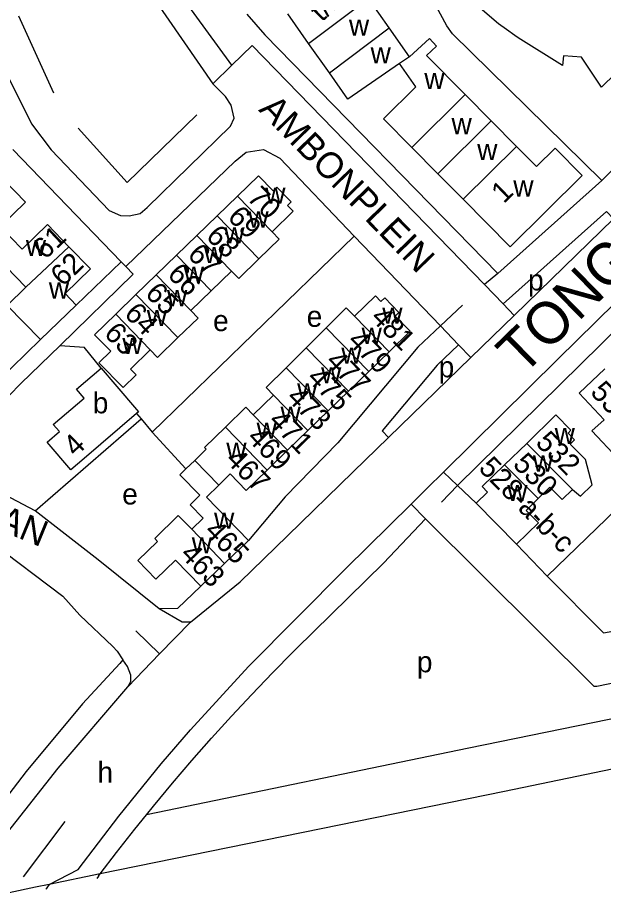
# Model space of a CAD drawing. Extents: x 162883 to 165538, y 383986 to 385172.
# Drawn here: x 163883.1 to 163994.9, y 384146.8 to 384315.2 of the extents above; entities that cross this region are included whole.
import ezdxf

# ---------------------------------------------------------------- set-up
doc = ezdxf.new("R2010")
doc.units = 0
for name, color, linetype in [('BLT_Basislijn', 7, 'Continuous'), ('BLT_Bebouwing', 7, 'Continuous'), ('BLT_Centroide', 7, 'Continuous'), ('BLT_Huisnummer', 7, 'Continuous'), ('BLT_Huisnummer_ tussenligend', 7, 'Continuous'), ('BLT_Huisnummer_reeks', 7, 'Continuous'), ('BLT_Onderverdeling_panden', 7, 'Continuous'), ('BLT_Spoorlijn', 7, 'Continuous'), ('BLT_Straatnaam', 7, 'Continuous'), ('BLT_Straatnaam_hoofdweg', 7, 'Continuous'), ('BLT_Vlakafsluiter', 7, 'Continuous')]:
    doc.layers.add(name, color=color, linetype=linetype)

msp = doc.modelspace()

# ---------------------------------------------------------------- linework, layer by layer
at = {"layer": 'BLT_Basislijn'}
for p, q in [((163924.02, 384306.15), (163911.31, 384323.59)), ((163907.2, 384321.69), (163920.41, 384302.58)), ((163883.27, 384315.54), (163889.98, 384300.83)), ((164013.39, 384302.89), (163994.61, 384284.11)), ((163904.06, 384283.71), (163917.36, 384296.67)), ((163894.71, 384294.1), (163904.06, 384283.71)), ((163994.61, 384284.11), (163974.78, 384266.34)), ((163908.8, 384236), (163947.38, 384273.48)), ((163947.38, 384273.48), (163963.83, 384256.31)), ((163902.88, 384268.59), (163894.31, 384260.31)), ((163905.2, 384266.19), (163891.22, 384252.56)), ((163903.78, 384267.65), (163905.2, 384266.19)), ((163974.78, 384266.34), (163972.26, 384264.24)), ((163972.26, 384264.24), (163975.8, 384260.54)), ((163963.83, 384256.31), (163968.04, 384260.27)), ((163975.8, 384260.54), (163977.91, 384258.34)), ((163977.91, 384258.34), (163973.76, 384254.31)), ((163963.83, 384256.31), (163967.29, 384252.7)), ((163887.47, 384253.7), (163868.57, 384235.37)), ((163967.29, 384252.7), (163969.61, 384250.27)), ((163891.22, 384252.56), (163883.77, 384245.29)), ((163891.22, 384252.56), (163895.81, 384252.24)), ((163899.07, 384248.22), (163895.81, 384252.24)), ((163883.77, 384245.29), (163873.86, 384235.34)), ((163905.84, 384239.57), (163906.68, 384238.56)), ((163886.45, 384221.02), (163906.68, 384238.56)), ((163906.68, 384238.56), (163908.8, 384236)), ((163908.8, 384236), (163915.24, 384229.02)), ((163967.06, 384225.86), (163964.42, 384228.4)), ((163964.03, 384222.68), (163967.06, 384225.86)), ((163967.06, 384225.86), (163970.63, 384222.44)), ((163960.99, 384219.5), (163958.21, 384222.27)), ((163952.95, 384210.99), (163960.99, 384219.5)), ((163978.37, 384214.61), (163984.22, 384208.51)), ((164150.83, 384212.71), (163969.22, 384175.66)), ((163936.27, 384194.64), (163952.95, 384210.99)), ((163910.21, 384193.65), (163905.67, 384198.1)), ((163969.22, 384175.66), (163907.73, 384162.95)), ((163892.13, 384161.68), (163884.18, 384151.08)), ((163898.55, 384151.18), (163898.25, 384150.79))]:
    msp.add_line(p, q, dxfattribs=at)
for points in [[(163994.61, 384284.11), (163966.15, 384312.12), (163965.02, 384313.63), (163953.02, 384335.9)], [(163964.42, 384228.4), (163986.24, 384250), (164052.16, 384314.79), (164056.26, 384318.57), (164060.48, 384321.02), (164065.34, 384323.67), (164071.72, 384327.14), (164076.99, 384329.2), (164083.5, 384330.4)], [(163876.85, 384317.63), (163876.52, 384315.19), (163876.84, 384312.69), (163885.77, 384294.95), (163889.52, 384289.93), (163900.58, 384278.38), (163902.75, 384277.42), (163904.42, 384277.33), (163906.5, 384277.82), (163907.83, 384278.92), (163923.76, 384294.47), (163924.46, 384295.99), (163923.89, 384298.48), (163922.81, 384300.12), (163920.41, 384302.58), (163924.02, 384306.15), (163927.87, 384309.86), (163972.26, 384264.24)], [(163926.89, 384315.85), (163930.34, 384311.93), (163974.78, 384266.34)], [(164059.74, 384310.76), (164056.87, 384313.63), (164032.27, 384289.87), (164016.59, 384274.64), (164006.24, 384264.42), (163967.06, 384225.86)], [(163882.2, 384290.04), (163902.88, 384268.59)], [(163903.78, 384267.65), (163924.62, 384287.8), (163926.76, 384289.52), (163930.06, 384290.05), (163933.15, 384288.39), (163947.38, 384273.48)], [(163996.88, 384276.8), (163995.5, 384278.19), (163975.8, 384260.54)], [(163977.91, 384258.34), (163996.88, 384276.8)], [(163902.88, 384268.59), (163903.78, 384267.65)], [(163963.83, 384256.31), (163959.54, 384252.25), (163944.24, 384234), (163934.22, 384223.65), (163927.17, 384215.32)], [(163967.29, 384252.7), (163963.19, 384248.82), (163952.67, 384236.27), (163953.91, 384235)], [(163953.91, 384235), (163969.61, 384250.27)], [(163916.1, 384199.7), (163925.6, 384207.45), (163934.66, 384216.25), (163947.17, 384228.45), (163953.91, 384235)], [(164027.9, 384231.44), (164003.06, 384226.79), (163984.22, 384208.51)], [(163809.91, 384223.64), (163827.65, 384226.73), (163840.62, 384227.24), (163852.31, 384225.57), (163862.35, 384222.93), (163868.9, 384220.05), (163877.87, 384215.17), (163891.74, 384204.67), (163895, 384201.09), (163901.33, 384195.06), (163902.14, 384194.16), (163903.2, 384192.56)], [(163886.45, 384221.02), (163876.2, 384226.44)], [(163958.21, 384222.27), (163961.31, 384225.34)], [(163889.17, 384149.64), (163894.69, 384152.48), (163902.47, 384162.68), (163910.55, 384172.64), (163916.13, 384179.15), (163927.18, 384191.23), (163945.77, 384209.95), (163958.21, 384222.27)], [(163910.14, 384202.27), (163898.51, 384211.66), (163886.45, 384221.02)], [(164116.02, 384212.73), (163993.66, 384187.45), (163993.19, 384187.45), (163960.99, 384219.5)], [(163984.22, 384208.51), (163994.93, 384197.66), (164005.58, 384199.58), (164032.87, 384204.99), (164031.84, 384208.94)], [(163918.11, 384206.59), (163913.64, 384202.31), (163910.15, 384202.27)], [(163916.1, 384199.7), (163914.52, 384199.7), (163910.14, 384202.27)], [(163907.73, 384162.95), (163909.06, 384164.6), (163912.69, 384168.97), (163916.38, 384173.29), (163920.13, 384177.56), (163923.94, 384181.77), (163927.81, 384185.93), (163931.74, 384190.04), (163935.72, 384194.09), (163936.27, 384194.64)], [(163903.2, 384192.56), (163902.64, 384191.81), (163895.5, 384184.1), (163884.75, 384171.2), (163881.42, 384166.88)], [(163904.19, 384187.35), (163904.73, 384188.4), (163904.71, 384189.58), (163904.11, 384191.27), (163903.2, 384192.56)], [(163875.55, 384146.78), (163880.5, 384158.68), (163890.85, 384171.85), (163904.19, 384187.35)], [(163898.89, 384151.63), (163901.99, 384155.7), (163905.49, 384160.17), (163907.73, 384162.95)], [(163898.55, 384151.18), (163898.89, 384151.63)], [(163888.55, 384148.77), (163888.54, 384148.75)], [(163889.17, 384149.64), (163888.71, 384149), (163888.55, 384148.77)]]:
    msp.add_lwpolyline(points, dxfattribs=at)
at = {"layer": 'BLT_Bebouwing'}
for p, q in [((163921.22, 384277.36), (163925.09, 384281.12)), ((163917.35, 384273.6), (163921.22, 384277.36)), ((163913.48, 384269.84), (163917.35, 384273.6)), ((163909.59, 384266.06), (163913.48, 384269.84)), ((163905.71, 384262.3), (163909.59, 384266.06)), ((163923.93, 384266.8), (163920.06, 384263.04)), ((163901.84, 384258.54), (163905.71, 384262.3)), ((163897.82, 384254.63), (163901.84, 384258.54)), ((163938.2, 384252.14), (163941.99, 384255.94)), ((163934.41, 384248.3), (163938.2, 384252.14)), ((163954.01, 384251.39), (163950.15, 384247.63)), ((163894.38, 384244.21), (163899.07, 384248.22)), ((163950.15, 384247.63), (163946.28, 384243.86)), ((163895.82, 384242.52), (163894.38, 384244.21)), ((163889.91, 384237.48), (163895.82, 384242.52)), ((163946.28, 384243.86), (163942.4, 384240.09)), ((163905.84, 384239.57), (163895.8, 384230.98)), ((163906.21, 384239.89), (163905.84, 384239.57)), ((163942.4, 384240.09), (163938.53, 384236.33)), ((163891.09, 384236.15), (163889.91, 384237.48)), ((163888.74, 384234.14), (163891.09, 384236.15)), ((163938.53, 384236.33), (163934.66, 384232.56)), ((163893.27, 384228.82), (163888.74, 384234.14)), ((163934.66, 384232.56), (163930.78, 384228.79)), ((163980.3, 384233.89), (163976.07, 384229.79)), ((163895.8, 384230.98), (163893.27, 384228.82)), ((163930.78, 384228.79), (163926.77, 384224.89)), ((163970.63, 384222.44), (163978.37, 384214.61)), ((163913.78, 384220.09), (163916.35, 384217.51)), ((163927.17, 384215.32), (163922.61, 384210.93)), ((163922.61, 384210.93), (163918.11, 384206.59))]:
    msp.add_line(p, q, dxfattribs=at)
for points in [[(163978.64, 384311.36), (163978.02, 384311.77), (163976.46, 384312.92), (163974.9, 384314.06), (163969.6, 384318.62), (163966.17, 384321.96), (163962.15, 384326.43), (163958.5, 384331.21), (163954.27, 384337.68), (163950.62, 384344.8), (163950.11, 384345.96)], [(163954.05, 384313.29), (163950.1, 384318.92)], [(163938.66, 384310.29), (163934.7, 384315.92)], [(163957.95, 384307.72), (163954.05, 384313.29)], [(163942.62, 384304.67), (163938.66, 384310.29)], [(163968.55, 384300.51), (163961.18, 384307.96), (163963.09, 384309.79), (163961.71, 384311.2), (163957.95, 384307.72)], [(164003.82, 384306.84), (163999.84, 384307.07), (163994.54, 384301.9), (163990.74, 384307.67), (163987.3, 384307.89), (163987.13, 384306.07), (163978.64, 384311.36)], [(163956.01, 384306.47), (163946.17, 384299.62), (163942.62, 384304.67)], [(163959.12, 384301.99), (163956.01, 384306.47)], [(163959.12, 384301.99), (163952.95, 384295.88), (163958.36, 384290.42)], [(163973.52, 384295.49), (163968.55, 384300.51)], [(163978.35, 384290.6), (163973.52, 384295.49)], [(163958.36, 384290.42), (163963.33, 384285.4)], [(163968.16, 384280.52), (163977.13, 384271.45), (163990.87, 384285.05), (163985.69, 384290.29), (163982.14, 384286.77), (163978.35, 384290.6)], [(163925.09, 384281.12), (163929.09, 384285), (163931.89, 384282.13), (163932.59, 384282.82), (163935.32, 384280.01), (163934.62, 384279.33), (163935.7, 384278.22), (163931.68, 384274.32)], [(163963.33, 384285.4), (163968.16, 384280.52)], [(163880.53, 384284.19), (163884.63, 384279.96), (163879.8, 384275.27), (163881.88, 384273.12)], [(163881.88, 384273.12), (163883.97, 384270.97), (163888.81, 384275.67), (163892.92, 384271.43)], [(163931.68, 384274.32), (163933.07, 384272.89), (163929.19, 384269.12)], [(163892.92, 384271.43), (163897.03, 384267.2), (163892.19, 384262.5), (163894.31, 384260.31)], [(163876.96, 384268.36), (163879.27, 384265.98), (163880.94, 384267.6), (163884.71, 384263.73)], [(163929.19, 384269.12), (163925.33, 384265.36), (163923.93, 384266.8)], [(163884.71, 384263.73), (163881.14, 384260.24), (163887.47, 384253.7)], [(163920.06, 384263.04), (163916.17, 384259.26)], [(163947.42, 384258.16), (163951.43, 384262.06), (163952.47, 384260.98), (163953.18, 384261.66), (163955.9, 384258.86), (163955.2, 384258.18), (163958.02, 384255.29), (163954.01, 384251.39)], [(163887.47, 384253.7), (163894.31, 384260.31)], [(163941.99, 384255.94), (163945.82, 384259.79), (163947.42, 384258.16)], [(163916.17, 384259.26), (163917.56, 384257.82), (163913.71, 384254.08)], [(163905.73, 384246.97), (163903.25, 384244.56), (163898.65, 384249.3), (163900.89, 384251.47), (163897.82, 384254.63)], [(163913.71, 384254.08), (163909.82, 384250.3), (163908.42, 384251.74)], [(163908.42, 384251.74), (163904.65, 384248.07), (163905.73, 384246.97)], [(163899.07, 384248.22), (163901.68, 384245.22), (163906.21, 384239.89)], [(163931.94, 384243.1), (163930.54, 384244.53), (163934.41, 384248.3)], [(163995.22, 384248.1), (163990.28, 384243.5), (163995.04, 384238.39), (163992.74, 384236.25), (163997.72, 384230.9), (164000, 384232.94), (164000.22, 384233.15), (163998.94, 384234.6), (164000, 384235.53), (164000.95, 384236.48), (163998.43, 384239.18), (164001.14, 384241.72)], [(163928.07, 384239.33), (163931.94, 384243.1)], [(163922.8, 384237), (163926.67, 384240.77)], [(163926.67, 384240.77), (163928.07, 384239.33)], [(163989.01, 384225.09), (163990.54, 384223.78), (163992.77, 384225.97), (163991.51, 384230.81), (163990.75, 384231.57), (163988.59, 384233.75), (163989.42, 384234.57), (163988.18, 384235.83), (163988.68, 384236.43), (163985.87, 384239.31), (163980.3, 384233.89)], [(163916.92, 384230.64), (163919.11, 384232.77), (163918.79, 384233.1), (163922.8, 384237)], [(163914.09, 384227.9), (163915.24, 384229.02)], [(163915.24, 384229.02), (163916.92, 384230.64)], [(163976.07, 384229.79), (163971.79, 384225.64), (163972.83, 384224.57), (163970.63, 384222.44)], [(163914.09, 384227.9), (163917.91, 384223.97), (163916.05, 384222.16), (163918.52, 384219.61), (163916.35, 384217.51)], [(163926.77, 384224.89), (163923.7, 384228.04), (163921.53, 384225.93)], [(163921.53, 384225.93), (163919.18, 384223.61)], [(163989.01, 384225.09), (163987.04, 384223.14), (163984.67, 384225.53), (163982.45, 384223.33)], [(163927.17, 384215.32), (163919.18, 384223.61)], [(163978.37, 384214.61), (163982.52, 384218.71), (163980.18, 384221.08), (163982.45, 384223.33)], [(163906.06, 384211.49), (163909.83, 384215.17), (163909.3, 384215.71), (163913.78, 384220.09)], [(163918.11, 384206.59), (163913.26, 384211.57), (163909.53, 384207.94), (163906.06, 384211.49)]]:
    msp.add_lwpolyline(points, dxfattribs=at)
at = {"layer": 'BLT_Onderverdeling_panden'}
for p, q in [((163938.66, 384310.29), (163950.1, 384318.92)), ((163942.62, 384304.67), (163954.05, 384313.29)), ((163957.95, 384307.72), (163956.01, 384306.47)), ((163968.55, 384300.51), (163958.36, 384290.42)), ((163973.52, 384295.49), (163963.33, 384285.4)), ((163978.35, 384290.6), (163968.16, 384280.52)), ((163925.09, 384281.12), (163931.68, 384274.32)), ((163921.22, 384277.36), (163929.19, 384269.12)), ((163917.35, 384273.6), (163923.93, 384266.8)), ((163892.92, 384271.43), (163884.71, 384263.73)), ((163913.48, 384269.84), (163920.06, 384263.04)), ((163909.59, 384266.06), (163916.17, 384259.26)), ((163905.71, 384262.3), (163913.71, 384254.08)), ((163901.84, 384258.54), (163908.42, 384251.74)), ((163947.42, 384258.16), (163954.01, 384251.39)), ((163941.99, 384255.94), (163950.15, 384247.63)), ((163938.2, 384252.14), (163946.28, 384243.86)), ((163934.41, 384248.3), (163942.4, 384240.09)), ((163931.94, 384243.1), (163938.53, 384236.33)), ((163928.07, 384239.33), (163934.66, 384232.56)), ((163922.8, 384237), (163930.78, 384228.79)), ((163989.01, 384225.09), (163980.3, 384233.89)), ((163916.92, 384230.64), (163921.53, 384225.93)), ((163982.45, 384223.33), (163976.07, 384229.79)), ((163916.35, 384217.51), (163922.61, 384210.93))]:
    msp.add_line(p, q, dxfattribs=at)
at = {"layer": 'BLT_Spoorlijn'}
for points in [[(164137.67, 384200.96), (163976.02, 384167.4)], [(163976.02, 384167.4), (163898.89, 384151.63)], [(163898.89, 384151.63), (163889.17, 384149.64)], [(163889.17, 384149.64), (163886.53, 384149.1), (163875.55, 384146.78)]]:
    msp.add_lwpolyline(points, dxfattribs=at)
at = {"layer": 'BLT_Vlakafsluiter'}
for p, q in [((163969.61, 384250.27), (163973.76, 384254.31)), ((163961.31, 384225.34), (163964.42, 384228.4)), ((163916.1, 384199.7), (163910.21, 384193.65)), ((163910.21, 384193.65), (163904.19, 384187.35))]:
    msp.add_line(p, q, dxfattribs=at)

# ---------------------------------------------------------------- texts
at = {"layer": 'BLT_Centroide'}
for s, p in [('w', (163946.36, 384311.78)), ('w', (163950.49, 384306.47)), ('w', (163960.75, 384301.55)), ('w', (163965.94, 384292.94)), ('w', (163970.84, 384288)), ('w', (163977.73, 384281.03)), ('w', (163930.39, 384279.66)), ('w', (163927.16, 384275.11)), ('w', (163922.58, 384272.09)), ('w', (163884.7, 384269.69)), ('w', (163918.7, 384268.31)), ('w', (163914.83, 384264.55)), ('p', (163980.55, 384263.09)), ('w', (163889.09, 384261.55)), ('w', (163911.64, 384260.08)), ('w', (163907.78, 384256.3)), ('w', (163952.72, 384256.73)), ('e', (163920.43, 384255.33)), ('e', (163938.3, 384256.14)), ('w', (163948.78, 384252.89)), ('w', (163903.12, 384250.95)), ('w', (163944.91, 384249.12)), ('p', (163963.49, 384246.5)), ('w', (163941.05, 384245.36)), ('w', (163936.47, 384242.31)), ('b', (163897.47, 384239.62)), ('w', (163933.3, 384237.83)), ('w', (163928.73, 384234.78)), ('w', (163985.62, 384233.78)), ('w', (163922.96, 384230.94)), ('w', (163981.47, 384228.5)), ('w', (163976.58, 384222.86)), ('e', (163903.09, 384222.21)), ('w', (163920.62, 384217.56)), ('w', (163916.36, 384212.88)), ('p', (163959.33, 384190.15)), ('h', (163898.37, 384169.05))]:
    msp.add_text(s, height=4, dxfattribs=at).set_placement(p)
at = {"layer": 'BLT_Huisnummer'}
for s, rotation, p in [('70', 314.7343, (163926.72, 384280.6)), ('69', 314.0915, (163923, 384276.93)), ('61', 43.2113, (163888.38, 384268.84)), ('67', 314.0915, (163915.35, 384269.74)), ('62', 44.1177, (163891.77, 384263.69)), ('65', 314.0915, (163907.27, 384262.32)), ('481', 314.0915, (163950.31, 384257.71)), ('63', 314.0915, (163899.43, 384254.69)), ('477', 314.0915, (163941.72, 384249.33)), ('534', 312.852, (163992.25, 384243.53)), ('473', 314.0915, (163934.26, 384242.44)), ('469', 314.0915, (163926.7, 384234.75)), ('532', 314.6835, (163981.78, 384233.85)), ('4', 44.0953, (163894.2, 384231.17)), ('465', 314.0915, (163918.58, 384216.91)), ('463', 314.0953, (163913.95, 384212.5))]:
    msp.add_text(s, height=4, rotation=rotation, dxfattribs=at).set_placement(p)
at = {"layer": 'BLT_Huisnummer_ tussenligend'}
for s, rotation, p in [('68', 314.0915, (163918.88, 384273.26)), ('66', 314.0915, (163911.52, 384265.98)), ('64', 314.0915, (163903.28, 384258.45)), ('479', 314.0915, (163945.89, 384253.26)), ('475', 314.0915, (163938.14, 384246.17)), ('471', 314.0915, (163930.81, 384237.98)), ('467', 314.0915, (163922.61, 384230.59)), ('530', 314.6835, (163977.45, 384229.7))]:
    msp.add_text(s, height=4, rotation=rotation, dxfattribs=at).set_placement(p)
at = {"layer": 'BLT_Huisnummer_reeks'}
for s, rotation, p in [('t/m', 44.0915, (163941.2, 384314.26)), ('1', 44.0915, (163975.89, 384279.56)), ('528-a-b-c', 314.6835, (163970.91, 384228.96))]:
    msp.add_text(s, height=4, rotation=rotation, dxfattribs=at).set_placement(p)
at = {"layer": 'BLT_Straatnaam'}
for s, rotation, p in [('AMBONPLEIN', 314.2723, (163928.96, 384297.5)), ('CERAMLAAN', 337.7378, (163849.05, 384229.81))]:
    msp.add_text(s, height=5, rotation=rotation, dxfattribs=at).set_placement(p)
at = {"layer": 'BLT_Straatnaam_hoofdweg'}
msp.add_text('TONGELRESESTRAAT', height=8, rotation=44.3284, dxfattribs=at).set_placement((163979.48, 384246.63))

doc.saveas('drawing.dxf')
